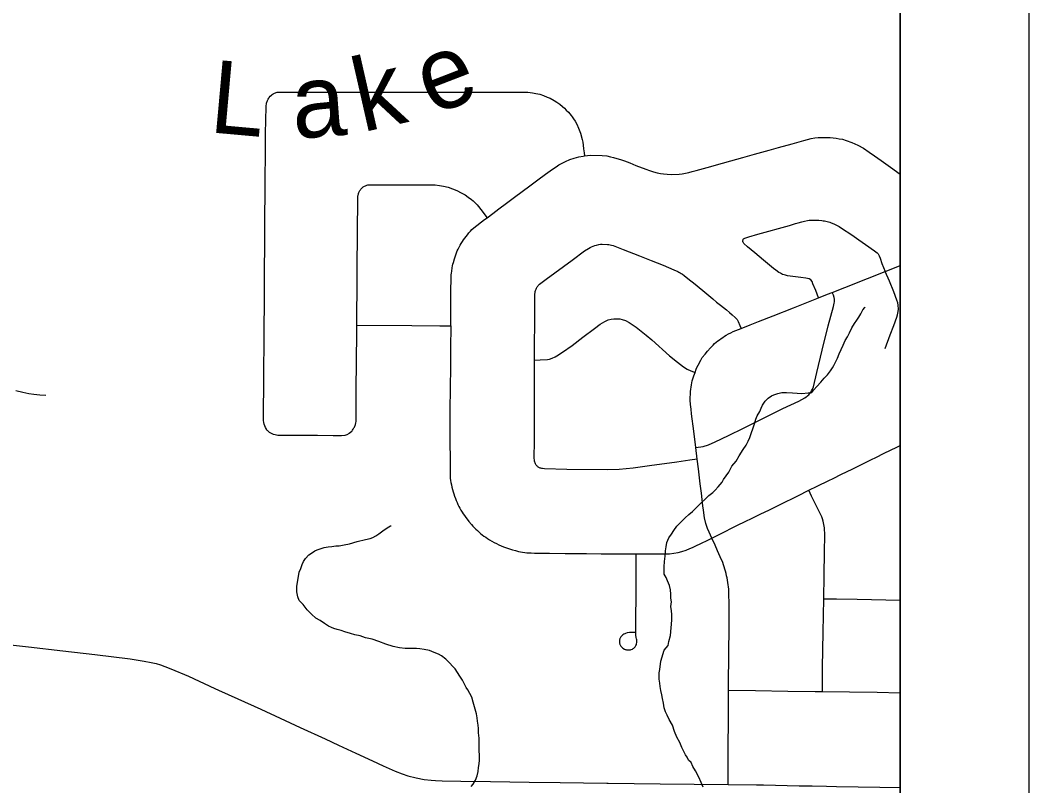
# Model space of a CAD drawing. Extents: x 0 to 34, y 0 to 22.
# Drawn here: x 8.215 to 9, y 15.806 to 16.402 of the extents above; entities that cross this region are included whole.
import ezdxf

# ---------------------------------------------------------------- set-up
doc = ezdxf.new("R2010")
doc.units = 0
for name, color, linetype in [('GM_X_City_Street', 7, 'Continuous'), ('GM_X_County_Road', 7, 'Continuous'), ('GM_X_County_Text', 7, 'Continuous'), ('GM_X_Minor_River', 7, 'Continuous'), ('GM_X_Rail_Line_Text', 7, 'Continuous'), ('SH_Cut_Line', 7, 'Continuous'), ('SH_Data', 7, 'Continuous')]:
    doc.layers.add(name, color=color, linetype=linetype)

msp = doc.modelspace()

# ---------------------------------------------------------------- linework, layer by layer
at = {"layer": 'GM_X_City_Street'}
for points in [[(8.47308, 16.08217), (8.47214, 16.08146), (8.4711, 16.08068), (8.46933, 16.07966), (8.46781, 16.07913), (8.4651, 16.07873), (8.4587, 16.07885), (8.44655, 16.07912), (8.4355, 16.07902), (8.41961, 16.0791), (8.41566, 16.07917), (8.41343, 16.07956), (8.41227, 16.07984), (8.41171, 16.08003), (8.41115, 16.08025), (8.41009, 16.08078), (8.40909, 16.08143), (8.40862, 16.08179), (8.40775, 16.08261), (8.40736, 16.08305), (8.40665, 16.08398), (8.40597, 16.08518), (8.40538, 16.08648), (8.40493, 16.08783), (8.40459, 16.08921), (8.4044, 16.09062), (8.40433, 16.09206), (8.40446, 16.09986), (8.40462, 16.1166), (8.40469, 16.1307), (8.40485, 16.15028), (8.40492, 16.16469), (8.40512, 16.18008), (8.40524, 16.19413), (8.40533, 16.20817), (8.40544, 16.2266), (8.40553, 16.24508), (8.40578, 16.27186), (8.406, 16.30511), (8.4061, 16.31107), (8.40623, 16.32749), (8.40637, 16.3316), (8.40654, 16.33571), (8.40669, 16.33707), (8.40683, 16.33773), (8.407, 16.3384), (8.40722, 16.33904), (8.40747, 16.33968), (8.40776, 16.3403), (8.40809, 16.34089), (8.40845, 16.34148), (8.40885, 16.34204), (8.40973, 16.34307)], [(8.40973, 16.34307), (8.41073, 16.34401), (8.41127, 16.34442), (8.41184, 16.34481), (8.41242, 16.34516), (8.41303, 16.34548), (8.41365, 16.34576), (8.41429, 16.346), (8.41494, 16.34621), (8.47898, 16.3463), (8.61013, 16.34617), (8.61383, 16.34575), (8.61644, 16.34527), (8.61939, 16.34458), (8.62229, 16.3436), (8.62529, 16.34246), (8.62747, 16.34152), (8.63057, 16.33977), (8.63275, 16.33853), (8.63505, 16.33677), (8.63713, 16.33502), (8.63858, 16.33377), (8.64007, 16.33232), (8.64167, 16.33063), (8.64275, 16.3293), (8.64373, 16.32809), (8.64464, 16.32701), (8.64576, 16.32547), (8.6469, 16.3237), (8.64837, 16.32121), (8.64965, 16.31829), (8.65118, 16.31424), (8.65251, 16.30935), (8.65292, 16.30733), (8.65325, 16.30502), (8.65355, 16.30211), (8.65389, 16.2991), (8.6542, 16.29665)], [(8.55012, 16.16437), (8.55023, 16.19008), (8.55037, 16.20267), (8.55049, 16.20408), (8.55066, 16.20548), (8.55086, 16.20688), (8.55137, 16.20964), (8.5516, 16.21096), (8.55188, 16.21227), (8.5522, 16.21357), (8.55301, 16.21646), (8.5535, 16.21803), (8.55404, 16.21959), (8.55462, 16.22114), (8.55524, 16.22267), (8.55591, 16.22417), (8.55663, 16.22566), (8.55745, 16.2271), (8.55831, 16.22853), (8.55921, 16.22994), (8.56013, 16.23131), (8.5611, 16.23267), (8.5621, 16.23401), (8.56313, 16.23531), (8.56424, 16.23666), (8.56539, 16.23798), (8.56657, 16.23926), (8.5682, 16.24064), (8.57641, 16.24707), (8.57836, 16.24856), (8.58288, 16.2519), (8.58759, 16.25541), (8.59343, 16.25977), (8.59966, 16.26439), (8.61173, 16.27339), (8.61789, 16.27801), (8.62397, 16.28235), (8.62935, 16.28639), (8.63216, 16.28817), (8.63437, 16.28968), (8.63678, 16.29103), (8.63932, 16.29233), (8.6429, 16.29374), (8.64624, 16.29493), (8.64993, 16.29596), (8.65313, 16.29654), (8.6542, 16.29665), (8.65664, 16.29694), (8.65904, 16.29709), (8.66798, 16.2969), (8.67163, 16.29658), (8.67433, 16.29599), (8.67678, 16.29546), (8.67941, 16.29473), (8.68235, 16.29383), (8.68523, 16.29273), (8.68938, 16.29112), (8.69425, 16.28925), (8.70194, 16.28628), (8.70489, 16.28518), (8.708, 16.28417), (8.71081, 16.28343), (8.71329, 16.28299), (8.71572, 16.28273), (8.71867, 16.28237), (8.72157, 16.28224), (8.72777, 16.28248), (8.73032, 16.28276), (8.73288, 16.28321), (8.73553, 16.28371), (8.73798, 16.28436), (8.74104, 16.28521), (8.74965, 16.2876), (8.76172, 16.29095), (8.76809, 16.29271), (8.77748, 16.2954), (8.7866, 16.29789), (8.79794, 16.30107), (8.80513, 16.3031), (8.81574, 16.30602), (8.82496, 16.30873), (8.83065, 16.31009), (8.83335, 16.31058), (8.83615, 16.31084), (8.83913, 16.31106), (8.84544, 16.3109), (8.84769, 16.31074), (8.85003, 16.31038), (8.85243, 16.30999), (8.85499, 16.30954), (8.85789, 16.30871), (8.86232, 16.30705), (8.86687, 16.30502), (8.8713, 16.3026), (8.87571, 16.2996), (8.87998, 16.29666), (8.88522, 16.29295), (8.8924, 16.28792), (8.9, 16.28249)], [(8.47308, 16.08217), (8.47374, 16.08314), (8.47432, 16.08393), (8.47485, 16.08499), (8.47517, 16.08558), (8.4755, 16.0863), (8.47573, 16.08682), (8.47599, 16.08767), (8.47619, 16.0888), (8.47643, 16.09005), (8.4765, 16.0933), (8.47666, 16.11247), (8.4768, 16.13881), (8.47694, 16.15722), (8.47701, 16.16495), (8.47711, 16.1755), (8.47719, 16.19138), (8.4774, 16.21369), (8.47753, 16.23209), (8.4776, 16.2404), (8.47775, 16.25995), (8.47796, 16.26499), (8.47812, 16.26624), (8.47826, 16.26685), (8.47843, 16.26746), (8.47865, 16.26806), (8.4789, 16.26863), (8.47918, 16.2692), (8.4795, 16.26974), (8.47986, 16.27026), (8.48024, 16.27077), (8.48066, 16.27124), (8.48111, 16.27169), (8.48159, 16.2721), (8.48208, 16.27249), (8.4826, 16.27284), (8.48315, 16.27316), (8.48371, 16.27344), (8.48429, 16.27369), (8.48489, 16.2739), (8.48549, 16.27408), (8.50059, 16.2742), (8.53791, 16.27403), (8.54144, 16.27365), (8.5446, 16.27316), (8.54815, 16.27234), (8.55151, 16.271), (8.55483, 16.26965), (8.5583, 16.26801), (8.56133, 16.26624), (8.56381, 16.26454), (8.56631, 16.26263), (8.56751, 16.26162), (8.5687, 16.26058), (8.56969, 16.25952), (8.57071, 16.25846), (8.57168, 16.25715), (8.57526, 16.25251), (8.5767, 16.25075), (8.57836, 16.24856)], [(8.83633, 16.18609), (8.83419, 16.19193), (8.83203, 16.19716), (8.8313, 16.1988), (8.83034, 16.2001), (8.82912, 16.20101), (8.8265, 16.20158), (8.82249, 16.20209), (8.8123, 16.20335), (8.81059, 16.20371), (8.80961, 16.20402), (8.80833, 16.20443), (8.8067, 16.20527), (8.80553, 16.20594), (8.80308, 16.2078), (8.80138, 16.209), (8.79349, 16.21557), (8.78677, 16.22111), (8.78098, 16.22587), (8.7783, 16.22852), (8.77794, 16.22894), (8.77766, 16.22944), (8.77754, 16.2298), (8.77746, 16.23038), (8.77764, 16.23146), (8.77781, 16.23179), (8.77802, 16.23211), (8.77888, 16.23269), (8.78202, 16.23358), (8.78913, 16.23565), (8.81376, 16.24256), (8.81846, 16.24393), (8.82061, 16.24453), (8.82338, 16.24544), (8.82554, 16.2459), (8.82771, 16.24633), (8.82898, 16.2465), (8.83026, 16.24663), (8.83155, 16.24671), (8.83668, 16.24659), (8.839, 16.24635), (8.84005, 16.24622), (8.84108, 16.24605), (8.84211, 16.24584), (8.84313, 16.24559), (8.84414, 16.2453), (8.84514, 16.24497), (8.84613, 16.24461), (8.84821, 16.24379), (8.84931, 16.24333), (8.8504, 16.24283), (8.85146, 16.24229), (8.85234, 16.24167), (8.85429, 16.24046), (8.8622, 16.23512), (8.86777, 16.23134), (8.87288, 16.22765), (8.87993, 16.22276), (8.88185, 16.22124), (8.88269, 16.2204), (8.88357, 16.21894), (8.88433, 16.217), (8.88567, 16.21287), (8.88832, 16.20668)], [(8.74193, 16.06067), (8.7362, 16.05981), (8.72609, 16.05831), (8.7049, 16.05552), (8.69211, 16.05374), (8.68111, 16.05263), (8.67201, 16.0524), (8.64046, 16.05271), (8.62298, 16.05317), (8.62147, 16.05332), (8.6209, 16.05342), (8.62036, 16.05355), (8.61981, 16.05373), (8.61929, 16.05394), (8.61878, 16.0542), (8.61829, 16.0545), (8.61783, 16.05483), (8.61739, 16.05519), (8.61699, 16.05559), (8.61661, 16.05601), (8.61627, 16.05647), (8.61599, 16.0571), (8.61575, 16.05773), (8.61554, 16.05838), (8.61537, 16.05904), (8.61524, 16.0597), (8.61507, 16.06174), (8.6152, 16.0747), (8.61542, 16.11228), (8.61534, 16.12598), (8.61527, 16.13779), (8.61545, 16.17877), (8.61558, 16.18893), (8.61571, 16.19022), (8.61596, 16.19116), (8.61612, 16.1918), (8.61631, 16.19242), (8.61655, 16.19304), (8.61681, 16.19364), (8.61711, 16.19423), (8.61745, 16.1948), (8.61781, 16.19534), (8.61821, 16.19587), (8.61864, 16.19637), (8.61909, 16.19684), (8.62432, 16.20066), (8.6447, 16.21546), (8.65427, 16.22277), (8.65734, 16.22466), (8.65855, 16.22532), (8.65979, 16.22591), (8.66106, 16.22643), (8.66237, 16.22688), (8.66368, 16.22725), (8.66536, 16.22761), (8.66669, 16.22781), (8.66804, 16.22793), (8.67212, 16.22779), (8.67314, 16.22764), (8.67414, 16.22745), (8.67512, 16.22721), (8.67641, 16.22682), (8.68427, 16.22373), (8.69697, 16.21874), (8.70621, 16.2151), (8.71541, 16.21149), (8.72362, 16.20808), (8.72678, 16.20662), (8.72773, 16.20614), (8.72865, 16.20562), (8.72956, 16.20507), (8.73044, 16.20449), (8.73188, 16.20343), (8.73604, 16.20027), (8.73896, 16.19787), (8.74191, 16.19548), (8.74789, 16.19052), (8.75094, 16.18798), (8.75399, 16.18545), (8.75705, 16.18291), (8.7601, 16.18037), (8.7624, 16.17856), (8.76468, 16.17672), (8.76694, 16.17484), (8.76916, 16.17293), (8.77136, 16.17099), (8.77291, 16.16926), (8.77392, 16.16772), (8.77519, 16.16464), (8.77603, 16.16238)], [(8.76596, 15.80743), (8.76607, 15.83135), (8.7663, 15.86263), (8.76641, 15.88092), (8.76661, 15.91341), (8.7667, 15.92596), (8.76684, 15.94595), (8.76667, 15.95779), (8.76652, 15.95952), (8.76633, 15.96123), (8.76609, 15.96295), (8.76554, 15.96641), (8.76521, 15.96816), (8.76484, 15.96991), (8.76443, 15.97164), (8.76397, 15.97337), (8.76348, 15.97509), (8.76294, 15.97679), (8.76237, 15.97848), (8.76176, 15.98015), (8.75981, 15.98471), (8.75785, 15.98927), (8.75589, 15.99381), (8.75336, 15.99926), (8.75119, 16.00375), (8.74996, 16.0066), (8.74862, 16.01045), (8.74754, 16.01491), (8.74682, 16.02097), (8.7464, 16.0244), (8.74589, 16.02925), (8.74532, 16.03409), (8.74428, 16.04149), (8.74285, 16.05304), (8.74193, 16.06067), (8.74078, 16.06983), (8.73919, 16.08234), (8.73752, 16.09599), (8.73712, 16.09952), (8.73668, 16.10323), (8.7365, 16.10665), (8.73679, 16.11335), (8.73702, 16.11509), (8.73723, 16.11674), (8.73748, 16.11839), (8.73779, 16.12002), (8.73812, 16.12164), (8.73851, 16.12326), (8.73918, 16.12551), (8.74024, 16.12819), (8.74123, 16.13078), (8.74165, 16.13186), (8.74267, 16.1338), (8.7447, 16.13769), (8.74591, 16.13969), (8.74801, 16.14236), (8.74984, 16.14462), (8.75217, 16.14737), (8.75432, 16.14947), (8.7555, 16.15056), (8.7567, 16.1516), (8.75793, 16.15261), (8.75919, 16.15358), (8.76048, 16.15452), (8.76179, 16.15542), (8.76313, 16.15628), (8.7645, 16.1571), (8.76626, 16.15806), (8.76804, 16.15898), (8.76983, 16.15986), (8.77603, 16.16238), (8.7831, 16.16513), (8.78974, 16.16776), (8.80111, 16.17226), (8.81685, 16.17845), (8.83633, 16.18609), (8.84328, 16.1889), (8.84702, 16.1904), (8.85673, 16.19417), (8.87441, 16.20121), (8.88832, 16.20668), (8.89664, 16.20996), (8.9, 16.21129)], [(8.88811, 16.14668), (8.89212, 16.1573), (8.895, 16.16476), (8.89731, 16.17123), (8.89782, 16.173), (8.89808, 16.1742), (8.89828, 16.17542), (8.89847, 16.17723), (8.89835, 16.18049), (8.89807, 16.18228), (8.89739, 16.18438), (8.89484, 16.19073), (8.89147, 16.19927), (8.88832, 16.20668)], [(8.74078, 16.06983), (8.74661, 16.07056), (8.75066, 16.07188), (8.75596, 16.07416), (8.76635, 16.07899), (8.77792, 16.08471), (8.78782, 16.08961), (8.80864, 16.09997), (8.82095, 16.1058), (8.82561, 16.10841), (8.82672, 16.10908), (8.82742, 16.10959), (8.82809, 16.11014), (8.82873, 16.11073), (8.82932, 16.11137), (8.82988, 16.11207), (8.83045, 16.11288), (8.83096, 16.11373), (8.83165, 16.11504), (8.83237, 16.11684), (8.83508, 16.1282), (8.8392, 16.14547), (8.84378, 16.16429), (8.84793, 16.17933), (8.8486, 16.18193), (8.84883, 16.18314), (8.8487, 16.18525), (8.84845, 16.18643), (8.84795, 16.18815), (8.84754, 16.18924), (8.84702, 16.1904)], [(8.61527, 16.13779), (8.61984, 16.13787), (8.62534, 16.13807), (8.62697, 16.13841), (8.62906, 16.13913), (8.63141, 16.14027), (8.6328, 16.14117), (8.6372, 16.14391), (8.64468, 16.1492), (8.65305, 16.15555), (8.66195, 16.16231), (8.66653, 16.1657), (8.67002, 16.16785), (8.67273, 16.16895), (8.67489, 16.16955), (8.67714, 16.16981), (8.67913, 16.16991), (8.68161, 16.16976), (8.68349, 16.1693), (8.68602, 16.16841), (8.6891, 16.16695), (8.69212, 16.16501), (8.69437, 16.16338), (8.70213, 16.15717), (8.70653, 16.15341), (8.72048, 16.14117), (8.72655, 16.13621), (8.73138, 16.13254), (8.73404, 16.13063), (8.73696, 16.12942), (8.74024, 16.12819)], [(8.47701, 16.16495), (8.51973, 16.16465), (8.54163, 16.16446), (8.55012, 16.16437)], [(8.55012, 16.16437), (8.54994, 16.14663), (8.54982, 16.13406), (8.54971, 16.11432), (8.54955, 16.10039), (8.54945, 16.08673), (8.54959, 16.04774), (8.54979, 16.04594), (8.55003, 16.04414), (8.55032, 16.04235), (8.55064, 16.04056), (8.55102, 16.03876), (8.55148, 16.03698), (8.55197, 16.03525), (8.55251, 16.03353), (8.55309, 16.03182), (8.55371, 16.03012), (8.55438, 16.02844), (8.55504, 16.0269), (8.55575, 16.02537), (8.5565, 16.02386), (8.55729, 16.02238), (8.55811, 16.02092), (8.55898, 16.01948), (8.55989, 16.01806), (8.56082, 16.01669), (8.56182, 16.01527), (8.56285, 16.01386), (8.56423, 16.0121), (8.56617, 16.00981), (8.56734, 16.00852), (8.56853, 16.00727), (8.5697, 16.00612), (8.57091, 16.00499), (8.57214, 16.0039), (8.5734, 16.00284), (8.57469, 16.00181), (8.576, 16.00081), (8.57733, 15.99985), (8.57869, 15.99892), (8.58042, 15.99786), (8.58217, 15.99684), (8.58394, 15.99586), (8.58573, 15.99491), (8.58754, 15.994), (8.58937, 15.99313), (8.59122, 15.9923), (8.59351, 15.99152), (8.59582, 15.99078), (8.59814, 15.99009), (8.60047, 15.98944), (8.60281, 15.98884), (8.60444, 15.98853), (8.60608, 15.98826), (8.60773, 15.98803), (8.60938, 15.98785), (8.61104, 15.98771), (8.61269, 15.98761), (8.61519, 15.98746), (8.62702, 15.98736), (8.6393, 15.98728), (8.65584, 15.98716), (8.66731, 15.98706), (8.69449, 15.98694), (8.72038, 15.98706), (8.72385, 15.98749), (8.72706, 15.98812), (8.73009, 15.9888), (8.73322, 15.98981), (8.73615, 15.99098), (8.73822, 15.99193), (8.74032, 15.99294), (8.74529, 15.99529), (8.74969, 15.99746), (8.75336, 15.99926), (8.76361, 16.00445), (8.76862, 16.00688), (8.77381, 16.00944), (8.77867, 16.01178), (8.78533, 16.01505), (8.79084, 16.01776), (8.79822, 16.02132), (8.80488, 16.0246), (8.81, 16.02715), (8.81654, 16.03033), (8.82221, 16.03315), (8.82674, 16.03536), (8.82878, 16.03639), (8.83528, 16.0396), (8.84438, 16.04408), (8.84764, 16.04569), (8.85416, 16.04887), (8.8625, 16.05295), (8.8708, 16.05705), (8.87752, 16.06033), (8.88082, 16.06194), (8.88741, 16.06521), (8.89228, 16.06761), (8.89716, 16.06994), (8.9, 16.07131)], [(8.21168, 16.11404), (8.21711, 16.11271), (8.22185, 16.11179), (8.2258, 16.11117), (8.23038, 16.11062), (8.23496, 16.11031)], [(8.83937, 15.87983), (8.83951, 15.89838), (8.84004, 15.92597), (8.84042, 15.95196), (8.84075, 15.97008), (8.84105, 15.9886), (8.84123, 16.00155), (8.84099, 16.00727), (8.84057, 16.00979), (8.83987, 16.01245), (8.83939, 16.01423), (8.83886, 16.01568), (8.83746, 16.01885), (8.83514, 16.02344), (8.83094, 16.03194), (8.82878, 16.03639)], [(8.69356, 15.92582), (8.68917, 15.92572), (8.68742, 15.92553), (8.68615, 15.92507), (8.68553, 15.92481), (8.68484, 15.9244), (8.68416, 15.92394), (8.68353, 15.92345), (8.68278, 15.92269), (8.68247, 15.92229), (8.6822, 15.92186), (8.68197, 15.92141), (8.68177, 15.92095), (8.68162, 15.92047), (8.6815, 15.91998), (8.68137, 15.91892), (8.68144, 15.91797), (8.68154, 15.91747), (8.68167, 15.91699), (8.68183, 15.91652), (8.68204, 15.91605), (8.68229, 15.91562), (8.68257, 15.91519), (8.68402, 15.91365), (8.68538, 15.9128), (8.68588, 15.91259), (8.68639, 15.91242), (8.68691, 15.91228), (8.68744, 15.91219), (8.69011, 15.91235), (8.69063, 15.9125), (8.69148, 15.91286), (8.69217, 15.9133), (8.6926, 15.91365), (8.69302, 15.91403), (8.69359, 15.91468), (8.69393, 15.91516), (8.69424, 15.91567), (8.69461, 15.91647), (8.6948, 15.91703), (8.695, 15.91789), (8.69507, 15.9185), (8.6949, 15.91995), (8.69465, 15.92085), (8.69445, 15.92176), (8.69418, 15.92357), (8.69408, 15.93384), (8.69416, 15.94018), (8.69432, 15.95087), (8.69445, 15.97929), (8.69449, 15.98694)], [(8.84042, 15.95196), (8.85027, 15.95183), (8.86634, 15.95162), (8.8888, 15.95115), (8.9, 15.95102)], [(8.76641, 15.88092), (8.7874, 15.8806), (8.81233, 15.88016), (8.83365, 15.8799), (8.83937, 15.87983), (8.86052, 15.87949), (8.88188, 15.87918), (8.9, 15.87891)]]:
    msp.add_lwpolyline(points, dxfattribs=at)
at = {"layer": 'GM_X_County_Road'}
msp.add_line((8.36666, 15.88218), (8.36935, 15.88097), dxfattribs=at)
for points in [[(8.20533, 15.91637), (8.22142, 15.91453), (8.24831, 15.91145), (8.27309, 15.90861), (8.30077, 15.90521), (8.31162, 15.90355), (8.31711, 15.9025), (8.32093, 15.90158), (8.32432, 15.90053), (8.32771, 15.89936), (8.33239, 15.89745), (8.34597, 15.89167), (8.36666, 15.88218)], [(8.36935, 15.88097), (8.38458, 15.87411), (8.40234, 15.86598), (8.41747, 15.85905), (8.43294, 15.85188), (8.45231, 15.84295), (8.46276, 15.83804), (8.47628, 15.83185), (8.48932, 15.82582), (8.49761, 15.82204), (8.50699, 15.81786), (8.51242, 15.81573), (8.51674, 15.81432), (8.5232, 15.81264), (8.52951, 15.81147), (8.53484, 15.81083), (8.5384, 15.81053)], [(8.5384, 15.81053), (8.5435, 15.81036), (8.55805, 15.81012), (8.58098, 15.80978), (8.61112, 15.80939), (8.63526, 15.80904)], [(8.63526, 15.80904), (8.67172, 15.8085), (8.67273, 15.80849)], [(8.67273, 15.80849), (8.71323, 15.80806), (8.76596, 15.80743), (8.788, 15.80717), (8.79353, 15.80707), (8.82131, 15.80644), (8.8315, 15.8063), (8.84259, 15.80606), (8.85028, 15.80598), (8.88413, 15.80541), (8.9, 15.80515)]]:
    msp.add_lwpolyline(points, dxfattribs=at)
at = {"layer": 'GM_X_County_Text'}
msp.add_lwpolyline([(6.61711, 15.32914), (8.9, 15.30473), (8.9, 20.9), (2.1, 20.9)], dxfattribs=at)
at = {"layer": 'GM_X_Minor_River'}
for points in [[(8.87075, 16.17681), (8.87227, 16.17871), (8.87265, 16.17909)], [(8.71733, 15.86401), (8.71619, 15.86705), (8.71581, 15.87085), (8.71505, 15.87427), (8.71429, 15.87731), (8.71353, 15.88073), (8.71314, 15.88377), (8.71276, 15.88643), (8.71238, 15.88947), (8.71238, 15.8944), (8.71276, 15.89707), (8.71352, 15.90353), (8.71617, 15.91189), (8.71921, 15.91569), (8.71997, 15.91873), (8.72111, 15.92329), (8.72224, 15.93545), (8.72224, 15.93963), (8.72186, 15.94267), (8.72148, 15.94609), (8.72186, 15.94951), (8.72147, 15.95255), (8.72147, 15.95559), (8.72109, 15.95901), (8.72033, 15.96243), (8.71881, 15.96585), (8.71767, 15.96851), (8.71614, 15.97116), (8.71614, 15.97383), (8.71614, 15.97686), (8.71652, 15.98104), (8.7169, 15.98522), (8.71728, 15.9894), (8.71766, 15.99244), (8.71842, 15.99586), (8.71993, 15.99929), (8.72183, 16.00233), (8.72373, 16.00499), (8.72601, 16.00841), (8.72943, 16.01183), (8.73247, 16.01487), (8.73551, 16.01753), (8.73817, 16.01981), (8.74007, 16.02171), (8.74235, 16.02399), (8.74463, 16.02628), (8.74843, 16.0297), (8.75109, 16.03236), (8.75413, 16.03464), (8.75603, 16.03654), (8.75831, 16.0392), (8.76134, 16.04262), (8.76248, 16.0449), (8.76438, 16.04756), (8.76666, 16.05061), (8.76894, 16.05517), (8.77236, 16.05897), (8.77464, 16.06315), (8.77768, 16.06809), (8.77996, 16.07151), (8.78147, 16.07455), (8.78299, 16.07759), (8.78641, 16.08823), (8.78755, 16.09165), (8.78869, 16.09431), (8.79058, 16.09773), (8.79172, 16.10039), (8.79286, 16.10268), (8.79476, 16.10572), (8.79704, 16.108), (8.7997, 16.1099), (8.8016, 16.11066), (8.80464, 16.1118), (8.80768, 16.11256), (8.81148, 16.11256), (8.81605, 16.11219), (8.82327, 16.11181), (8.82821, 16.11219), (8.83125, 16.11257), (8.83277, 16.11447), (8.83505, 16.11714), (8.83809, 16.12056), (8.84075, 16.1236), (8.8434, 16.12626), (8.84568, 16.1293), (8.8472, 16.13158), (8.84834, 16.13348), (8.84948, 16.13614), (8.851, 16.13918), (8.85252, 16.1426), (8.85404, 16.14602), (8.85556, 16.14944), (8.85707, 16.15286), (8.85897, 16.1559), (8.86049, 16.15895), (8.86239, 16.16275), (8.86429, 16.16617), (8.86619, 16.16883), (8.86771, 16.17111), (8.86923, 16.17377), (8.87075, 16.17681)], [(8.56608, 15.8058), (8.5676, 15.8077), (8.5695, 15.81074), (8.57064, 15.81416), (8.5714, 15.81758), (8.57178, 15.82063), (8.57216, 15.82366), (8.57254, 15.82633), (8.57254, 15.83013), (8.57215, 15.83392), (8.57215, 15.83886), (8.57215, 15.84342), (8.57177, 15.84761), (8.57177, 15.85102), (8.57139, 15.85368), (8.571, 15.85672), (8.57062, 15.85938), (8.57024, 15.86242), (8.56757, 15.87154), (8.56643, 15.87534), (8.56491, 15.87838), (8.56339, 15.88104), (8.56225, 15.88294), (8.56073, 15.8856), (8.55921, 15.88864), (8.5573, 15.89168), (8.5554, 15.89472), (8.5535, 15.89737), (8.5516, 15.89965), (8.54932, 15.90193), (8.54628, 15.90497), (8.54285, 15.90763), (8.54057, 15.90877), (8.53715, 15.91029), (8.53373, 15.9118), (8.52955, 15.91256), (8.52613, 15.91294), (8.52347, 15.91332), (8.52118, 15.91332), (8.51852, 15.91332), (8.51472, 15.91332), (8.51016, 15.91369), (8.50522, 15.91483), (8.49952, 15.91673), (8.4942, 15.91863), (8.48887, 15.92052), (8.48393, 15.92166), (8.47975, 15.92318), (8.47557, 15.92394), (8.47215, 15.92508), (8.46759, 15.92622), (8.46492, 15.92735), (8.46188, 15.92811), (8.45922, 15.92887), (8.45732, 15.92963), (8.45504, 15.93077), (8.452, 15.93267), (8.44858, 15.93495), (8.44516, 15.93685), (8.44173, 15.93988), (8.43831, 15.9433), (8.43527, 15.94748), (8.43223, 15.95052), (8.43108, 15.95356), (8.43032, 15.95736), (8.43032, 15.96154), (8.43222, 15.97256), (8.43335, 15.9756), (8.43449, 15.97864), (8.43563, 15.98092), (8.43715, 15.9832), (8.43981, 15.98624), (8.44171, 15.98738), (8.44437, 15.98928), (8.44627, 15.99004), (8.44931, 15.99118), (8.45159, 15.99195), (8.45463, 15.99233), (8.45767, 15.99271), (8.46071, 15.99309), (8.46338, 15.99309), (8.46718, 15.99385), (8.47135, 15.99461), (8.47744, 15.99652), (8.4839, 15.99804), (8.48732, 15.9988), (8.4896, 15.99956), (8.49188, 16.00108), (8.49416, 16.00261), (8.4972, 16.00489), (8.50062, 16.00717), (8.50328, 16.00869), (8.50366, 16.00869)], [(8.74663, 15.8055), (8.74511, 15.80892), (8.7432, 15.8131), (8.74054, 15.81804), (8.73864, 15.82146), (8.73712, 15.8245), (8.73521, 15.8264), (8.73407, 15.82868), (8.73293, 15.83058), (8.73141, 15.83324), (8.72989, 15.83628), (8.72837, 15.84007), (8.72609, 15.84425), (8.72418, 15.84881), (8.72266, 15.85375), (8.72, 15.85793), (8.71848, 15.86135), (8.71733, 15.86401)]]:
    msp.add_lwpolyline(points, dxfattribs=at)
at = {"layer": 'SH_Cut_Line'}
msp.add_lwpolyline([(6.61711, 15.32914), (8.9, 15.30473), (8.9, 20.9), (2.1, 20.9)], dxfattribs=at)
at = {"layer": 'SH_Data'}
for p, q in [((9, 21), (9, 14)), ((8.9, 20.9), (8.9, 14.1))]:
    msp.add_line(p, q, dxfattribs=at)

# ---------------------------------------------------------------- texts
at = {"layer": 'GM_X_Rail_Line_Text'}
for s, rotation, p in [('e', 21.11576, (8.53548, 16.32787)), ('k', 12.8247, (8.48128, 16.31486)), ('L', 354.87628, (8.36138, 16.31508)), ('a', 4.28208, (8.42814, 16.30994))]:
    msp.add_text(s, height=0.05663, rotation=rotation, dxfattribs=at).set_placement(p)

doc.saveas('drawing.dxf')
